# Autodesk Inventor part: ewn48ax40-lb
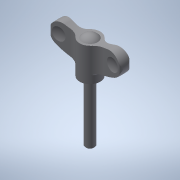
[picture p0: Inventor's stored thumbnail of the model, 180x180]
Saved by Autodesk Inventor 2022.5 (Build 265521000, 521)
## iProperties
Created: 2016-12
Part Number: ewn48ax40-lb
Material: 一般
Document SubType Name: Modeling
Designer: imaocorp
Density: 1 g/cm^3
Appearance: 既定
Author: imaocorp
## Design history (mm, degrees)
node "ewn48ax40-lb.x_t1"
node "ewn48ax40-lb"
node "Base1"
